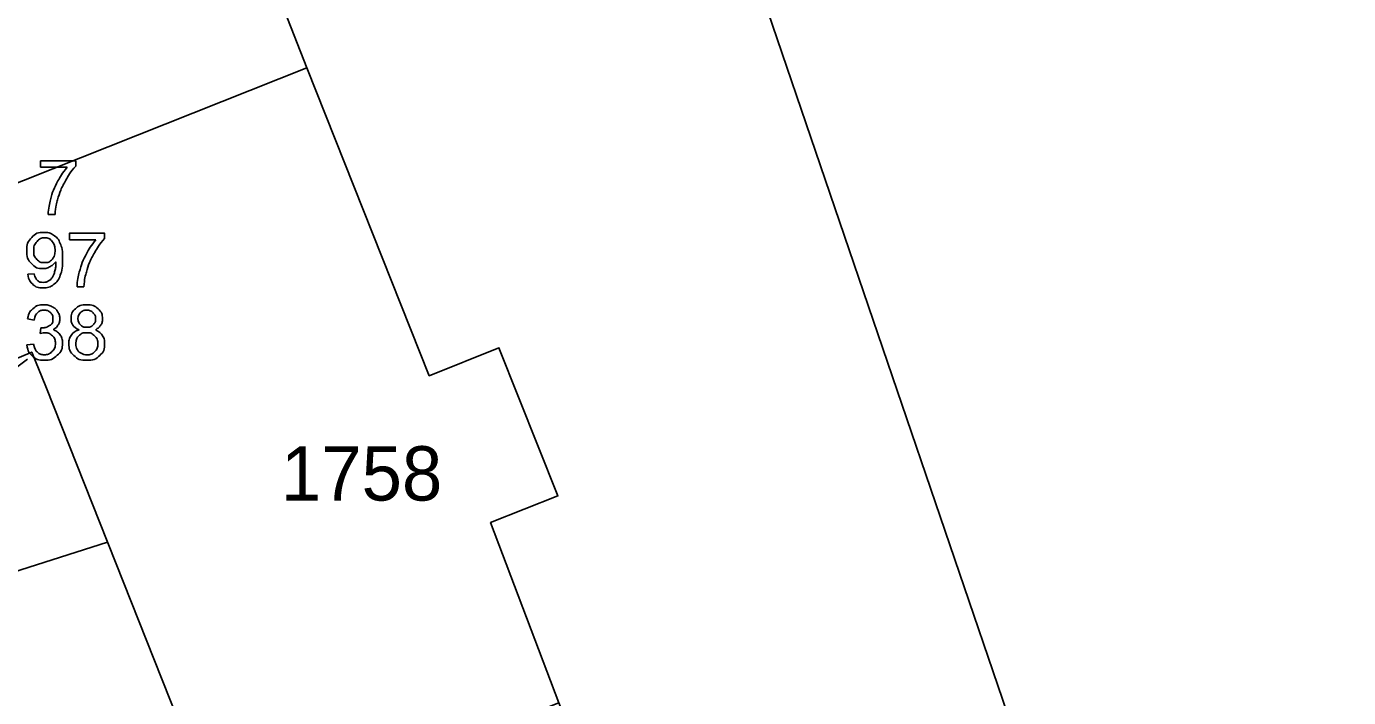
# Model space of a CAD drawing. Extents: x -562248 to -562040, y -1079385 to -1079027.
# Drawn here: x -562087.3 to -562050.73, y -1079214.81 to -1079196.27 of the extents above; entities that cross this region are included whole.
import ezdxf

# ---------------------------------------------------------------- set-up
doc = ezdxf.new("R2010")
doc.units = 0
for name, color, linetype in [('Kanalizační přípojka', 7, 'Continuous'), ('Parcela-polygon', 7, 'Continuous'), ('Parcela-text', 7, 'Continuous'), ('Popis šachty', 7, 'Continuous'), ('Vodovodní přípojka', 7, 'Continuous')]:
    doc.layers.add(name, color=color, linetype=linetype)

msp = doc.modelspace()

# ---------------------------------------------------------------- linework, layer by layer
at = {"layer": 'Kanalizační přípojka'}
msp.add_lwpolyline([(-562087.27, -1079205.46), (-562092.611, -1079209.439)], dxfattribs=at)
at = {"layer": 'Parcela-polygon'}
msp.add_line((-562050.734, -1079242.89), (-562081.378, -1079153.144), dxfattribs=at)
for points in [[(-562096.6, -1079181.53), (-562087.31, -1079177.84), (-562084.66, -1079184.52), (-562082.74, -1079183.76), (-562081.12, -1079187.88), (-562082.98, -1079188.64), (-562079.54, -1079197.41), (-562089.73, -1079201.46), (-562091.4, -1079197.27), (-562090.48, -1079196.9)], [(-562079.54, -1079197.41), (-562076.16, -1079205.92), (-562074.23, -1079205.15), (-562072.6, -1079209.24), (-562074.46, -1079209.98), (-562072.57, -1079214.96), (-562081.83, -1079218.64), (-562086.76, -1079206.22), (-562087.15, -1079205.27), (-562088.06, -1079205.65), (-562089.73, -1079201.46)]]:
    msp.add_lwpolyline(points, close=True, dxfattribs=at)
msp.add_lwpolyline([(-562087.31, -1079177.84), (-562084.66, -1079184.52), (-562082.74, -1079183.76), (-562081.12, -1079187.88), (-562082.98, -1079188.64), (-562079.54, -1079197.41), (-562076.16, -1079205.92), (-562074.23, -1079205.15), (-562072.6, -1079209.24), (-562074.46, -1079209.98), (-562072.57, -1079214.96), (-562069.67, -1079222.27), (-562067.79, -1079221.53), (-562066.16, -1079225.6), (-562068.03, -1079226.3), (-562065.74, -1079232.15), (-562074.99, -1079235.83), (-562081.83, -1079218.64), (-562086.76, -1079206.22), (-562087.15, -1079205.27), (-562088.06, -1079205.65)], dxfattribs=at)
at = {"layer": 'Popis šachty'}
for points in [[(-562086.907, -1079200.163), (-562086.907, -1079199.986), (-562085.936, -1079199.986), (-562085.936, -1079200.129)], [(-562086.173, -1079200.163), (-562086.907, -1079200.163)], [(-562086.508, -1079201.467), (-562086.697, -1079201.467)], [(-562086.109, -1079202.163), (-562086.109, -1079201.986), (-562085.138, -1079201.986), (-562085.138, -1079202.129)], [(-562085.375, -1079202.163), (-562086.109, -1079202.163)], [(-562087.259, -1079203.119), (-562087.082, -1079203.103)], [(-562085.71, -1079203.467), (-562085.9, -1079203.467)], [(-562087.083, -1079204.383), (-562087.267, -1079204.35)], [(-562086.922, -1079204.756), (-562086.902, -1079204.594)], [(-562087.285, -1079205.069), (-562087.101, -1079205.045)]]:
    msp.add_lwpolyline(points, dxfattribs=at)
for points in [[(-562085.936, -1079200.129), (-562086.079, -1079200.282), (-562086.22, -1079200.535), (-562086.36, -1079200.787), (-562086.437, -1079201.054), (-562086.492, -1079201.243), (-562086.508, -1079201.467)], [(-562086.697, -1079201.467), (-562086.694, -1079201.29), (-562086.628, -1079201.039), (-562086.561, -1079200.788), (-562086.437, -1079200.556), (-562086.313, -1079200.323), (-562086.173, -1079200.163)], [(-562087.082, -1079203.103), (-562087.059, -1079203.228), (-562086.996, -1079203.285), (-562086.933, -1079203.341), (-562086.834, -1079203.341), (-562086.749, -1079203.341), (-562086.685, -1079203.302), (-562086.621, -1079203.263), (-562086.58, -1079203.198), (-562086.539, -1079203.133), (-562086.512, -1079203.022), (-562086.484, -1079202.912), (-562086.484, -1079202.797), (-562086.484, -1079202.785), (-562086.485, -1079202.76), (-562086.54, -1079202.848), (-562086.636, -1079202.903), (-562086.732, -1079202.958), (-562086.843, -1079202.958), (-562087.029, -1079202.958), (-562087.158, -1079202.823), (-562087.287, -1079202.688), (-562087.287, -1079202.467), (-562087.287, -1079202.239), (-562087.152, -1079202.1), (-562087.018, -1079201.961), (-562086.815, -1079201.961), (-562086.669, -1079201.961), (-562086.548, -1079202.04), (-562086.427, -1079202.118), (-562086.364, -1079202.264), (-562086.301, -1079202.41), (-562086.301, -1079202.686), (-562086.301, -1079202.973), (-562086.363, -1079203.144), (-562086.426, -1079203.314), (-562086.549, -1079203.403), (-562086.672, -1079203.492), (-562086.838, -1079203.492), (-562087.014, -1079203.492), (-562087.125, -1079203.394), (-562087.237, -1079203.296), (-562087.259, -1079203.119)], [(-562086.506, -1079202.458), (-562086.506, -1079202.299), (-562086.59, -1079202.206), (-562086.674, -1079202.113), (-562086.793, -1079202.113), (-562086.916, -1079202.113), (-562087.006, -1079202.213), (-562087.097, -1079202.314), (-562087.097, -1079202.473), (-562087.097, -1079202.616), (-562087.011, -1079202.706), (-562086.925, -1079202.796), (-562086.798, -1079202.796), (-562086.67, -1079202.796), (-562086.588, -1079202.706), (-562086.506, -1079202.616), (-562086.506, -1079202.458)], [(-562085.9, -1079203.467), (-562085.897, -1079203.29), (-562085.83, -1079203.039), (-562085.764, -1079202.788), (-562085.639, -1079202.556), (-562085.515, -1079202.323), (-562085.375, -1079202.163)], [(-562085.138, -1079202.129), (-562085.282, -1079202.282), (-562085.422, -1079202.535), (-562085.563, -1079202.787), (-562085.639, -1079203.054), (-562085.695, -1079203.243), (-562085.71, -1079203.467)], [(-562087.267, -1079204.35), (-562087.233, -1079204.164), (-562087.114, -1079204.063), (-562086.994, -1079203.961), (-562086.816, -1079203.961), (-562086.693, -1079203.961), (-562086.589, -1079204.014), (-562086.486, -1079204.066), (-562086.431, -1079204.157), (-562086.377, -1079204.248), (-562086.377, -1079204.35), (-562086.377, -1079204.447), (-562086.429, -1079204.527), (-562086.481, -1079204.607), (-562086.583, -1079204.654), (-562086.45, -1079204.684), (-562086.377, -1079204.781), (-562086.303, -1079204.877), (-562086.303, -1079205.023), (-562086.303, -1079205.219), (-562086.447, -1079205.355), (-562086.59, -1079205.492), (-562086.809, -1079205.492), (-562087.006, -1079205.492), (-562087.137, -1079205.374), (-562087.267, -1079205.256), (-562087.285, -1079205.069)], [(-562086.902, -1079204.594), (-562086.884, -1079204.596), (-562086.872, -1079204.596), (-562086.755, -1079204.596), (-562086.66, -1079204.535), (-562086.566, -1079204.474), (-562086.566, -1079204.346), (-562086.566, -1079204.245), (-562086.635, -1079204.178), (-562086.703, -1079204.112), (-562086.812, -1079204.112), (-562086.919, -1079204.112), (-562086.991, -1079204.18), (-562087.063, -1079204.247), (-562087.083, -1079204.383)], [(-562085.837, -1079204.653), (-562085.952, -1079204.611), (-562086.008, -1079204.533), (-562086.063, -1079204.455), (-562086.063, -1079204.347), (-562086.063, -1079204.184), (-562085.946, -1079204.072), (-562085.828, -1079203.961), (-562085.633, -1079203.961), (-562085.437, -1079203.961), (-562085.317, -1079204.075), (-562085.198, -1079204.189), (-562085.198, -1079204.352), (-562085.198, -1079204.456), (-562085.253, -1079204.534), (-562085.307, -1079204.611), (-562085.419, -1079204.653), (-562085.281, -1079204.698), (-562085.208, -1079204.798), (-562085.136, -1079204.898), (-562085.136, -1079205.037), (-562085.136, -1079205.23), (-562085.272, -1079205.361), (-562085.408, -1079205.492), (-562085.63, -1079205.492), (-562085.852, -1079205.492), (-562085.988, -1079205.36), (-562086.124, -1079205.229), (-562086.124, -1079205.032), (-562086.124, -1079204.886), (-562086.049, -1079204.787), (-562085.975, -1079204.688), (-562085.837, -1079204.653)], [(-562085.874, -1079204.341), (-562085.874, -1079204.447), (-562085.806, -1079204.514), (-562085.738, -1079204.582), (-562085.629, -1079204.582), (-562085.522, -1079204.582), (-562085.455, -1079204.515), (-562085.388, -1079204.448), (-562085.388, -1079204.351), (-562085.388, -1079204.25), (-562085.457, -1079204.181), (-562085.526, -1079204.112), (-562085.631, -1079204.112), (-562085.736, -1079204.112), (-562085.805, -1079204.179), (-562085.874, -1079204.247), (-562085.874, -1079204.341)], [(-562087.101, -1079205.045), (-562087.07, -1079205.201), (-562086.994, -1079205.271), (-562086.918, -1079205.34), (-562086.808, -1079205.34), (-562086.677, -1079205.34), (-562086.588, -1079205.25), (-562086.499, -1079205.16), (-562086.499, -1079205.027), (-562086.499, -1079204.9), (-562086.582, -1079204.817), (-562086.665, -1079204.735), (-562086.792, -1079204.735), (-562086.845, -1079204.735), (-562086.922, -1079204.756)], [(-562085.934, -1079205.034), (-562085.934, -1079205.113), (-562085.897, -1079205.186), (-562085.86, -1079205.26), (-562085.787, -1079205.3), (-562085.713, -1079205.341), (-562085.628, -1079205.341), (-562085.496, -1079205.341), (-562085.411, -1079205.256), (-562085.326, -1079205.171), (-562085.326, -1079205.04), (-562085.326, -1079204.907), (-562085.414, -1079204.82), (-562085.502, -1079204.733), (-562085.635, -1079204.733), (-562085.765, -1079204.733), (-562085.849, -1079204.819), (-562085.934, -1079204.905), (-562085.934, -1079205.034)]]:
    msp.add_open_spline(points, degree=3, dxfattribs=at)
at = {"layer": 'Vodovodní přípojka'}
msp.add_lwpolyline([(-562096.777, -1079214.665), (-562096.597, -1079214.58), (-562092.26, -1079212.81), (-562085.06, -1079210.52)], dxfattribs=at)

# ---------------------------------------------------------------- texts
at = {"layer": 'Parcela-text'}
msp.add_text('1758', height=1.5, dxfattribs=at).set_placement((-562080.26, -1079209.37))

doc.saveas('drawing.dxf')
